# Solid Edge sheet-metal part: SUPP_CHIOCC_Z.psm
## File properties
Author: f_grande
Template: Normal.psm
Last saved by: f_grande
Revision: 9
Application: Solid Edge
Accuracy: 0,990
Material Thickness: 2,00 mm
Bend Radius: 1,00 mm
Relief Width: 1,00 mm
Relief Length: 0,00 mm
Neutral Factor: 0,330
Minimum Arc Length: 0,10 mm
Deviational Tolerance: 0,10 mm
Tipo di contenuto documento: 0
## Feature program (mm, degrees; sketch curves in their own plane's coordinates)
base tab "unnamed BaseTab 1"
flange "Lembo_2"
sketch for "Foro_1" plane through (0, -1.5, 0) normal (0, 0, -1) x-axis (-1, 0, 0)
  hole centre (10, 16.5) bore radius 2.5
hole "Foro_1"
sketch for "unnamed Hole 1" plane through (0, -1.5, 0) normal (0, 0, -1) x-axis (-1, 0, 0)
  hole centre (10, -18.5) bore radius 2.5
hole "unnamed Hole 1"
sketch for "unnamed Hole 2" plane through (0, -1.5, 0) normal (0, 0, -1) x-axis (-1, 0, 0)
  hole centre (-10, -18.5) bore radius 2.5
hole "unnamed Hole 2"
sketch for "unnamed Hole 3" plane through (0, -1.5, 0) normal (0, 0, -1) x-axis (-1, 0, 0)
  hole centre (-10, 16.5) bore radius 2.5
hole "unnamed Hole 3"
pattern "unnamed Pattern 1" of "Foro_1", "unnamed Hole 1", "unnamed Hole 2", "unnamed Hole 3"
sketch for "Foro_5" plane through (0, 30, 27.5) normal (0, 1, 0) x-axis (0, 0, -1)
hole "Foro_5"
sketch for "ExtrudedCutout_1" plane through (0, 30, 27.5) normal (0, 1, 0) x-axis (0, 0, -1)
extrude "ExtrudedCutout_1" cut
base feature "unnamed BaseFeature 1"
flat feature "unnamed FlatFeature 1"
Other named dimensions: "Modello_Campitura_sviluppata": CutSizeX = 108.6075 mm; CutSizeY = 40 mm
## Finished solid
Body 1: solid body, 20 faces, 50 edges, 28 vertices.
  Faces by surface: plane 13, cylinder 7
  Edges by curve: line 36, circle 14
Bounding box of the edges (mm): 40.000 x 60.000 x 52.000, from (-20, -30, 0) to (20, 30, 52).
Cylindrical faces by radius (mm): R1 x1, R2.5 x4, R3 x1, R14 x1
Planar faces by outward normal: +x 4, +y 1, +z 3, -x 1, -y 2, -z 2
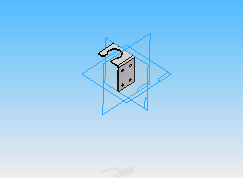
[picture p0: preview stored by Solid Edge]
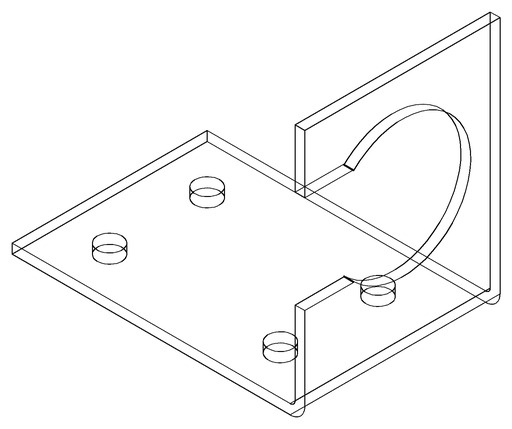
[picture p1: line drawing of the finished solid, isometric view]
